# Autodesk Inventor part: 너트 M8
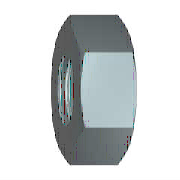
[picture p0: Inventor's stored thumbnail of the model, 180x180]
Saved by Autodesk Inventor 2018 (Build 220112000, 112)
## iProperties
IsCustomPart: 1
Created: 2012-02
Part Number: 너트 M8
Material: 강철, 연강
Description: 6각 너트 및 6각 가는 너트 - 이중 모따기
Document SubType Name: Modeling
Standard: KS B 1012
Designer: mduedu
Standards Organization: KS
Language: ko-KR
Size Designation: A M8
Categories: <MemberInstance><Categories><Category DisplayName="조임쇠" InternalName="e4da775c-781d-43d5-af7c-5136215cf5a6" Mnemonic="FSTN"><Category DisplayName="너트" InternalN
Density: 7.86 g/cm^3
Mass: 3.42669 g
Surface Area: 4.61759 cm^2
Volume: 0.435966 cm^3
Appearance: 강철
Author: mduedu
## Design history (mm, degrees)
sketch "스케치1"
  geometry: L1 (-7.506, 0)-(-3.753, 6.5); L2 (-3.753, 6.5)-(3.753, 6.5); L3 (3.753, 6.5)-(7.506, 0); L4 (7.506, 0)-(3.753, -6.5); L5 (3.753, -6.5)-(-3.753, -6.5); L6 (-3.753, -6.5)-(-7.506, 0); 2 further points
  constraints: 12 end point, 1 coincident, 1 horizontal, 11 other
  dimensions: "d0" = 15.01111 distance of L3.end L1.start (= 1.1547 x SW)
extrude "본체" new body sketch "스케치1" distance "d1" = 4 (= KOH); taper "d2" = 0 deg
sketch "스케치2"
  geometry: L1 (0, 3.753)-(0, 7.506) reference; L2 (0, 7.506)-(4, 7.506) reference; L3 (4, 3.753)-(4, 7.506) reference; L4 (-0.8, 0)-(4.8, 0) reference; L5 (0.581, 7.506)-(0, 6.5); L6 (3.419, 7.506)-(4, 6.5)
  constraints: 4 end point, 4 point on line
  dimensions: "d3" = 30 deg angle of L1 L5 (= ANG1); "d4" = 30 deg angle of L3 L6 (= ANG2); "d5" = 13 diameter of L5.end L4 (= SW0); "d6" = 13 diameter of L6.end L4 (= SW01)
revolve "모따기1" sketch "스케치2" stored, may be unused: angle "d7" = 90 deg
sketch "스케치3"
  geometry: A1 r 6.5 centre (0, 0) between (-3.25, -5.629) and (3.25, -5.629) reference; 1 further point
  constraints: 1 coincident
hole "스레드" sketch "스케치3" at (0, 0) diameter "d25" = 6.647; stored, may be unused: countersink angle "d29" = 82 deg, drill point angle "d31" = 118 deg; dims "d26" = 6, "d27" = 4, "d28" = 2, "d30" = 8
workaxis "Work Axis1"
workplane "Work Plane1"
body "Solid1"
chamfer "모따기2" distance "d8" = 0.67658 (= -0.5 x GD1 + 0.5 x NND); stored, may be unused: angle "d9" = 30 deg, second distance "d40" = 0.67658 (= -0.5 x GD1 + 0.5 x NND)
chamfer "모따기3" distance "d10" = 0.67658 (= -0.5 x GD1 + 0.5 x NND); stored, may be unused: angle "d11" = 30 deg, second distance "d41" = 0.67658 (= -0.5 x GD1 + 0.5 x NND)
other parameters: "ANG1" = 30 deg [user parameter; used in 1 equation term], "ANG2" = 30 deg [user parameter; used in 1 equation term], "NND" = 8 [user parameter; used in 4 equation terms], "KOH" = 4 [user parameter; used in 1 equation term], "SW" = 13 [user parameter; used in 4 equation terms], "SW0" = 13 (= SW) [user parameter; used in 1 equation term], "SW01" = 13 (= SW) [user parameter; used in 1 equation term], "GD1" = 6.64684 (computed from THREADDIA, PTC, TOA) [user parameter; used in 4 equation terms], "d13" = 0, "d14" = 0, "d39" = 0, "d42" = 0, "GUL" = 0.67658 (= 0.541266 x PTC) [user parameter], "TPU" = 8 (computed from PTC) [user parameter], "THREADDIA" = 8 [user parameter; used in 1 equation term], "TOA" = 30 deg [user parameter; used in 1 equation term], "PTC" = 1.25 [user parameter; used in 4 equation terms], "E0" = 15.015 (= 1.155 x SW) [user parameter], "GAL" = 0.67658 (= 0.541266 x PTC) [user parameter]
